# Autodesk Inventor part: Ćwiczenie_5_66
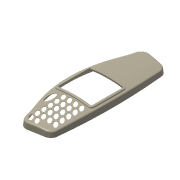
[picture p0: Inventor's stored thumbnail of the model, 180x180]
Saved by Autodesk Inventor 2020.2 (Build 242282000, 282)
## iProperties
Created: 2005-06
Part Number: Ćwiczenie_5_66
Document SubType Name: Modeling
Designer: F.Stasiak
Manufacturer: Standard
Standards Organization: Custom
Density: 1 g/cm^3
Material: Ogólny
Appearance: Jasnobeżowa
Manager: www.cadconsulting.pl
Company: Fabian Stasiak CAD Consulting
Author: F.Stasiak
Subject: Zbiór ćwiczeń. Autodesk Inventor 2020. Kurs podstawowy
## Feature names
1. Wyciągnięcie proste1 [Extrusion]
2. Zaokrąglenie1 [Fillet]
3. Zaokrąglenie2 [Fillet]
4. Skorupa1
5. Wyciągnięcie proste2 [Extrusion]
6. Zaokrąglenie3 [Fillet]
7. Zaokrąglenie4 [Fillet]
8. Wyciągnięcie proste5 [Extrusion]
9. Otwór pod klawisz [Extrusion]
10. Szyk otworów pod klawisze [Rectangular Pattern]
11. Wyciągnięcie proste6 [Extrusion]
## Parameters: d2 = 20 deg, d6 = 25 mm, d7 = 35 mm, d9 = -5 deg, d13 = 0, d14 = 2 mm, d15 = 0.5 mm, d16 = 12 mm, d17 = 1.5 mm, d18 = 1.5 mm, d19 = 25 mm, d20 = 25 mm, d22 = 0, d23 = 4 mm, d24 = 1.5 mm, d25 = 3 mm, d26 = 1 mm, d27 = 15 mm, d28 = 5 mm, d29 = 2.5 mm, d30 = 31 mm, d31 = 13 mm, d33 = 0, d43 = 0, d52 = 9 mm, d55 = 8.5 mm, d57 = 0, d58 = 0
